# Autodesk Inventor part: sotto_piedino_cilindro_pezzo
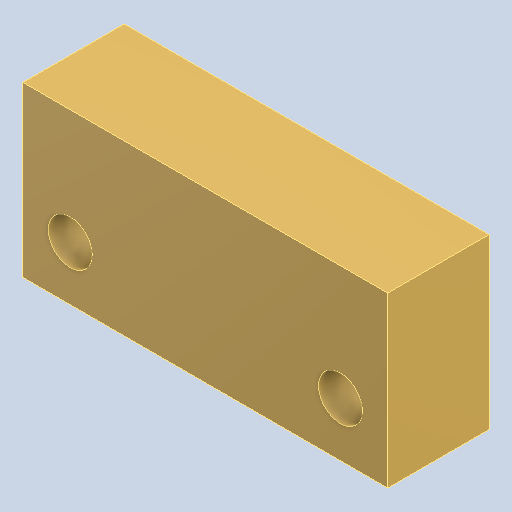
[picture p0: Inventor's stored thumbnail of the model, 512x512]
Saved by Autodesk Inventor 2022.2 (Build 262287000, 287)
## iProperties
Created: 2024-10
Part Number: sotto_piedino_cilindro_pezzo
Material: Generico
Document SubType Name: Modeling
Designer: 18907419
Density: 1 g/cm^3
Appearance: Default
Author: 18907419
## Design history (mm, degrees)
feature "Solido1"
node "Solido2"
